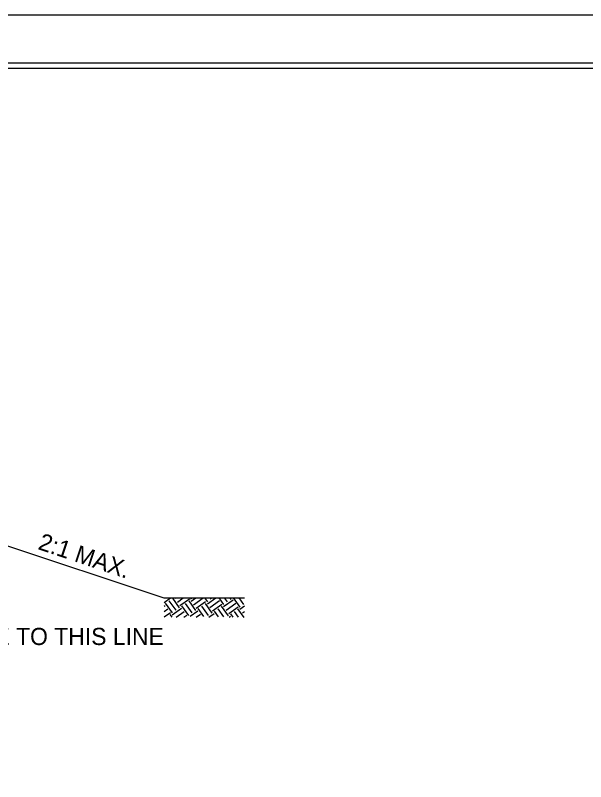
# Model space of a CAD drawing. Extents: x 3025871 to 3026431, y 707165 to 707825.
# Drawn here: x 3026178.1 to 3026218.3, y 707333.3 to 707387.4 of the extents above; entities that cross this region are included whole.
import ezdxf

# ---------------------------------------------------------------- set-up
doc = ezdxf.new("R2010")
doc.units = 0
for name, color, linetype in [('Old_Level_39', 7, 'Continuous'), ('Prop Drainage Structure Junction Box with Slab Lid TB 840 34 CELL', 7, 'Continuous'), ('Sheet Cutting Line CELL', 7, 'Continuous'), ('Typical Terminator CELL', 7, 'Continuous'), ('Typical Text Grade Point CELL', 7, 'Continuous')]:
    doc.layers.add(name, color=color, linetype=linetype)

msp = doc.modelspace()

# ---------------------------------------------------------------- linework, layer by layer
at = {"layer": 'Old_Level_39'}
msp.add_lwpolyline([(3026273.948, 707384.017), (3026023.973, 707384.017), (3026023.973, 707225.752), (3026273.948, 707225.752)], close=True, dxfattribs=at)
at = {"layer": 'Sheet Cutting Line CELL'}
msp.add_lwpolyline([(3026272.073, 707383.635), (3026047.073, 707383.635), (3026047.073, 707226.135), (3026272.073, 707226.135)], close=True, dxfattribs=at)
at = {"layer": 'Typical Terminator CELL'}
msp.add_lwpolyline([(3026274.623, 707387.385), (3026022.023, 707387.385), (3026022.023, 707222.385), (3026274.623, 707222.385)], close=True, dxfattribs=at)
at = {"layer": 'Typical Text Grade Point CELL'}
for p, q in [((3026175.573, 707350.633), (3026188.573, 707346.299)), ((3026188.573, 707346.299), (3026194.257, 707346.299)), ((3026188.573, 707346.299), (3026194.257, 707346.299)), ((3026188.594, 707345.97), (3026189.054, 707346.3)), ((3026188.594, 707345.97), (3026189.054, 707346.3)), ((3026189.685, 707345.613), (3026189.204, 707346.281)), ((3026189.685, 707345.613), (3026189.204, 707346.281)), ((3026189.348, 707346.258), (3026189.408, 707346.301)), ((3026189.348, 707346.258), (3026189.408, 707346.301)), ((3026189.528, 707346.007), (3026189.939, 707346.303)), ((3026189.528, 707346.007), (3026189.939, 707346.303)), ((3026189.708, 707345.757), (3026190.376, 707346.237)), ((3026189.708, 707345.757), (3026190.376, 707346.237)), ((3026190.52, 707346.213), (3026190.455, 707346.304)), ((3026190.52, 707346.213), (3026190.455, 707346.304)), ((3026190.497, 707346.07), (3026190.824, 707346.305)), ((3026190.497, 707346.07), (3026190.824, 707346.305)), ((3026190.677, 707345.819), (3026191.345, 707346.299)), ((3026190.677, 707345.819), (3026191.345, 707346.299)), ((3026191.669, 707346.025), (3026191.466, 707346.307)), ((3026191.669, 707346.025), (3026191.466, 707346.307)), ((3026191.645, 707345.882), (3026192.24, 707346.309)), ((3026191.645, 707345.882), (3026192.24, 707346.309)), ((3026191.919, 707346.205), (3026191.846, 707346.308)), ((3026191.919, 707346.205), (3026191.846, 707346.308)), ((3026192.818, 707345.837), (3026192.486, 707346.299)), ((3026192.818, 707345.837), (3026192.486, 707346.299)), ((3026193.068, 707346.017), (3026192.857, 707346.311)), ((3026193.068, 707346.017), (3026192.857, 707346.311)), ((3026193.319, 707346.198), (3026193.246, 707346.299)), ((3026193.319, 707346.198), (3026193.246, 707346.299)), ((3026193.966, 707345.649), (3026193.499, 707346.299)), ((3026193.966, 707345.649), (3026193.499, 707346.299)), ((3026194.217, 707345.829), (3026193.879, 707346.299)), ((3026194.217, 707345.829), (3026193.879, 707346.299)), ((3026188.594, 707345.716), (3026188.679, 707345.778)), ((3026188.594, 707345.716), (3026188.679, 707345.778)), ((3026189.183, 707345.253), (3026188.703, 707345.921)), ((3026189.183, 707345.253), (3026188.703, 707345.921)), ((3026189.434, 707345.433), (3026188.954, 707346.101)), ((3026189.434, 707345.433), (3026188.954, 707346.101)), ((3026190.332, 707345.065), (3026189.852, 707345.733)), ((3026190.332, 707345.065), (3026189.852, 707345.733)), ((3026190.583, 707345.245), (3026190.102, 707345.913)), ((3026190.583, 707345.245), (3026190.102, 707345.913)), ((3026190.833, 707345.425), (3026190.353, 707346.093)), ((3026190.833, 707345.425), (3026190.353, 707346.093)), ((3026190.857, 707345.569), (3026191.525, 707346.049)), ((3026190.857, 707345.569), (3026191.525, 707346.049)), ((3026191.731, 707345.057), (3026191.251, 707345.725)), ((3026191.731, 707345.057), (3026191.251, 707345.725)), ((3026191.982, 707345.237), (3026191.502, 707345.905)), ((3026191.982, 707345.237), (3026191.502, 707345.905)), ((3026191.825, 707345.631), (3026192.494, 707346.111)), ((3026191.825, 707345.631), (3026192.494, 707346.111)), ((3026192.006, 707345.38), (3026192.674, 707345.861)), ((3026192.006, 707345.38), (3026192.674, 707345.861)), ((3026193.131, 707345.049), (3026192.65, 707345.717)), ((3026193.131, 707345.049), (3026192.65, 707345.717)), ((3026192.794, 707345.694), (3026193.462, 707346.174)), ((3026192.794, 707345.694), (3026193.462, 707346.174)), ((3026192.974, 707345.443), (3026193.643, 707345.923)), ((3026192.974, 707345.443), (3026193.643, 707345.923)), ((3026193.943, 707345.506), (3026194.257, 707345.732)), ((3026193.943, 707345.506), (3026194.257, 707345.732)), ((3026188.594, 707345.336), (3026188.86, 707345.527)), ((3026188.594, 707345.336), (3026188.86, 707345.527)), ((3026188.594, 707344.956), (3026189.04, 707345.276)), ((3026188.594, 707344.956), (3026189.04, 707345.276)), ((3026189.16, 707345.109), (3026189.828, 707345.589)), ((3026189.16, 707345.109), (3026189.828, 707345.589)), ((3026189.452, 707344.939), (3026190.008, 707345.339)), ((3026189.452, 707344.939), (3026190.008, 707345.339)), ((3026190.428, 707345.007), (3026190.977, 707345.401)), ((3026190.428, 707345.007), (3026190.977, 707345.401)), ((3026191.401, 707344.987), (3026191, 707345.545)), ((3026191.401, 707344.987), (3026191, 707345.545)), ((3026191.744, 707344.939), (3026192.126, 707345.213)), ((3026191.744, 707344.939), (3026192.126, 707345.213)), ((3026192.43, 707344.967), (3026192.149, 707345.357)), ((3026192.43, 707344.967), (3026192.149, 707345.357)), ((3026192.815, 707344.959), (3026192.4, 707345.537)), ((3026192.815, 707344.959), (3026192.4, 707345.537)), ((3026193.154, 707345.192), (3026193.823, 707345.673)), ((3026193.154, 707345.192), (3026193.823, 707345.673)), ((3026193.458, 707344.946), (3026193.298, 707345.169)), ((3026193.458, 707344.946), (3026193.298, 707345.169)), ((3026193.844, 707344.938), (3026193.549, 707345.349)), ((3026193.844, 707344.938), (3026193.549, 707345.349)), ((3026194.229, 707344.931), (3026193.799, 707345.529)), ((3026194.229, 707344.931), (3026193.799, 707345.529)), ((3026194.123, 707345.255), (3026194.257, 707345.351)), ((3026194.123, 707345.255), (3026194.257, 707345.351)), ((3026189.155, 707344.939), (3026189.016, 707345.133)), ((3026189.155, 707344.939), (3026189.016, 707345.133)), ((3026189.981, 707344.939), (3026190.188, 707345.088)), ((3026189.981, 707344.939), (3026190.188, 707345.088)), ((3026190.862, 707344.939), (3026191.157, 707345.151)), ((3026190.862, 707344.939), (3026191.157, 707345.151)), ((3026193.172, 707344.952), (3026193.274, 707345.025)), ((3026193.172, 707344.952), (3026193.274, 707345.025))]:
    msp.add_line(p, q, dxfattribs=at)

# ---------------------------------------------------------------- texts
at = {"layer": 'Prop Drainage Structure Junction Box with Slab Lid TB 840 34 CELL'}
msp.add_text('GRADE TO THIS LINE', height=1.20892, dxfattribs=at).set_placement((3026171.955, 707342.98))
at = {"layer": 'Typical Text Grade Point CELL'}
msp.add_text('2:1 MAX.', height=1.2089, rotation=341.5651, dxfattribs=at).set_placement((3026179.636, 707349.752))

doc.saveas('drawing.dxf')
